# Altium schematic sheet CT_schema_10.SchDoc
size 274 x 160 mm
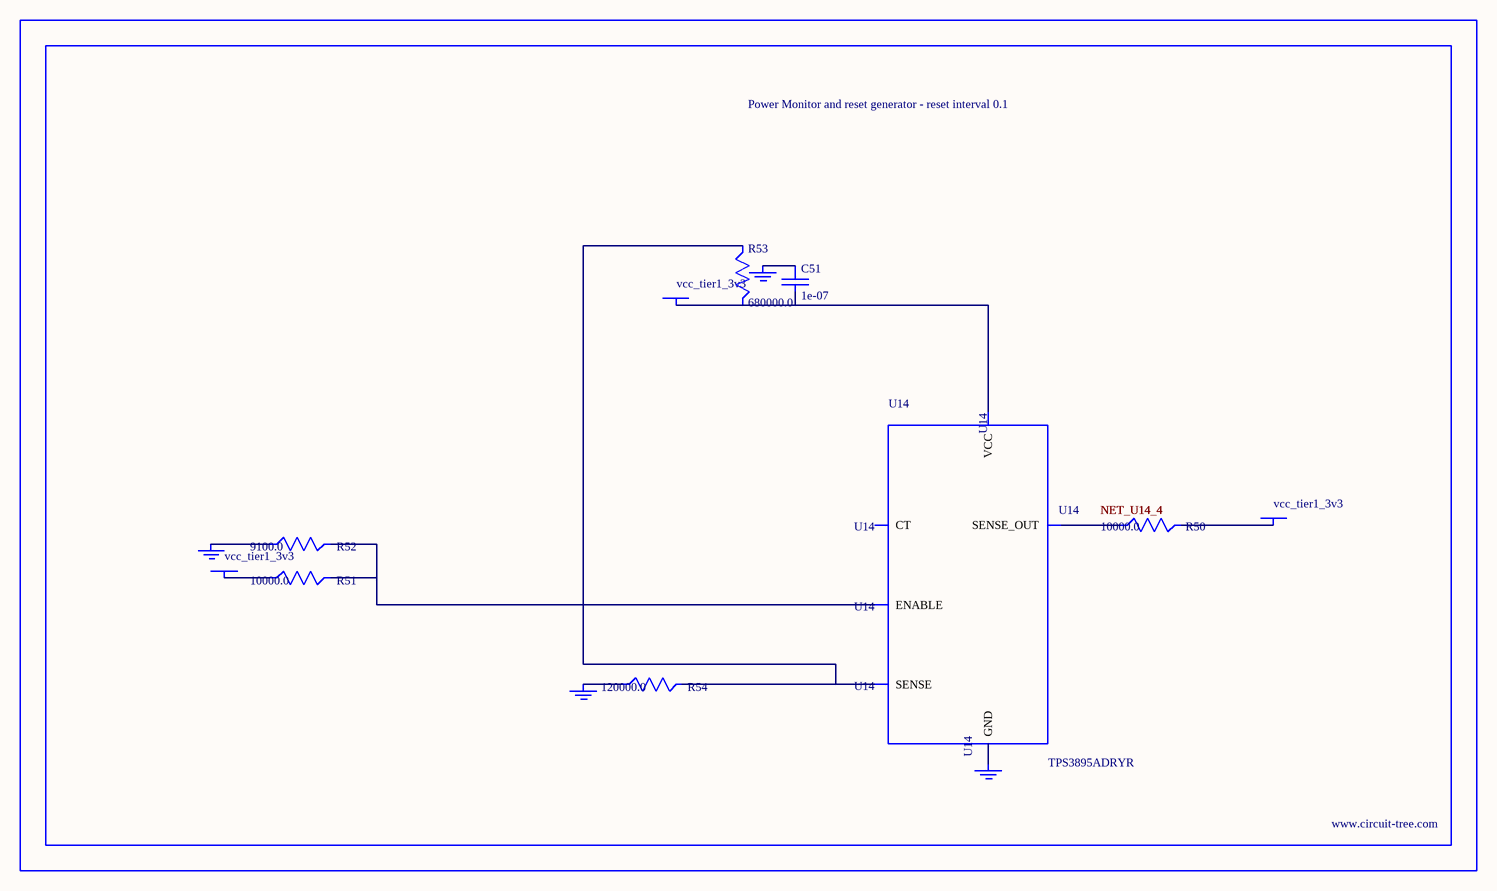
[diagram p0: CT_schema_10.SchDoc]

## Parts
BORDER9  (no value)
C51  1e-07  [C0402]
GND_INSTANCE_9_0  (no value)
GND_INSTANCE_9_1  (no value)
GND_INSTANCE_9_2  (no value)
GND_INSTANCE_9_3  (no value)
POWER_INSTANCE_9_0  vcc_tier1_3v3
POWER_INSTANCE_9_1  vcc_tier1_3v3
POWER_INSTANCE_9_2  vcc_tier1_3v3
R50  10000.0  [R0603]
R51  10000.0  [R0603]
R52  9100.0  [R0603]
R53  680000.0  [R0603]
R54  120000.0  [R0603]
U14  TPS3895ADRYR  [SON-6]

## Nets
NetC51_1: C51.1 GND_INSTANCE_9_2.0(GND)
NetC51_2: C51.2 POWER_INSTANCE_9_2.0(PWR) R53.2 U14.6(VCC)
NetGND_INSTANCE_9_0_0: GND_INSTANCE_9_0.0(GND) R52.1
NetGND_INSTANCE_9_1_0: GND_INSTANCE_9_1.0(GND) R54.1
NetGND_INSTANCE_9_3_0: GND_INSTANCE_9_3.0(GND) U14.2(GND)
NetPOWER_INSTANCE_9_0_0: POWER_INSTANCE_9_0.0(PWR) R51.1
NetPOWER_INSTANCE_9_1_0: POWER_INSTANCE_9_1.0(PWR) R50.2
NetR50_1: R50.1 U14.4(SENSE_OUT)
NetR51_2: R51.2 R52.2 U14.1(ENABLE)
NetR53_1: R53.1 R54.2 U14.3(SENSE)

Not connected (* = marked no-connect by the designer): U14 5(CT)

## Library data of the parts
BORDER9 = BORDER_PAGE9
C51 = C0402C104K3RACTU
GND_INSTANCE_9_0-GND_INSTANCE_9_3 = GND
POWER_INSTANCE_9_0-POWER_INSTANCE_9_2 = PWR
R50 R51 = RC0603JR-0710KL
R52 = RC0603JR-079K1L
R53 = RC0603JR-07680KL
R54 = RC0603JR-07120KL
